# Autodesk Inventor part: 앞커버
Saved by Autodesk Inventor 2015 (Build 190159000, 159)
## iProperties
Created: 2025-06
Part Number: 앞커버
Material: 일반
Document SubType Name: Modeling
Designer: 104
Density: 1 g/cm^3
Appearance: 기본값
Author: 104
Author: jhkim
Creation Date: 2025-05-23
Sending System: Autodesk Inventor 2026
Preprocessor: ST-DEVELOPER v20.1
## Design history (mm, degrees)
node "앞커버1"
node "솔리드1"
node "기준1"
